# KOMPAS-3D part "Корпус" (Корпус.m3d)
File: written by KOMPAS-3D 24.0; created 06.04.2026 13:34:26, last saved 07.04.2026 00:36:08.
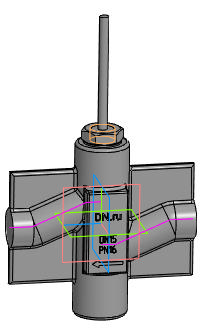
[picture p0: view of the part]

Document properties: Автор: R2D2; Полное имя файла: E:\Работа\Зайцев\Солянка\VSR1-13V-PED-F Клапан запорно-регулирующий DN.ru\DN15\DN15 Kv0.16\исходные материалы\Корпус.m3d

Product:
- Body: Труба / Нестандартная труба / L = 62.8 мм  | qty 1
    Материал: Нестандартная труба (density 7856 kg/m3)
    Масса: 1.53897
    Раздел спецификации: Детали
    Примечание: 0,24 кг
    additional columns: Pipeline; 0.025; 0; 0; 0.002; 0.06281; true; 0.04
- Body: Труба / Нестандартная труба / L = 62.8 мм  | qty 1
    Материал: Нестандартная труба (density 7856 kg/m3)
    Масса: 1.53897
    Раздел спецификации: Детали
    Форматы листов документа: БЧ
    Примечание: 0,24 кг
    additional columns: Pipeline; 0.025; 0; 0; 0.002; 0.06281; true; 0.04
- Component [standard]: Гайка М16-6H ГОСТ 5916-70  | qty 1  | Масса: 0.01768; Рассекать на разрезах: no; source file: C:\Program Files\ASCON\KOMPAS-3D v24\Libs\PolynomLib\DATA\vault\Methods\Kompas\3D\PLib_Nut_OST92_900.m3d
- Part/product: Корпус
    Масса: 1.53897

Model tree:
1. Эскиз:1
2. Труба:1  (labels: {F703FF30-5BE6-4673-A7F1-8EDA1BE1E2D1}; SHAPEOBJECT3D_ATTR_BUTT; SHAPEOBJECT3D_ATTR_VALID; SHAPEOBJECT3D_ATTR_BUTT_AREA)
     PIPE_D = 25; PIPE_R = 7
3. Труба:2  (labels: {F703FF30-5BE6-4673-A7F1-8EDA1BE1E2D1}; SHAPEOBJECT3D_ATTR_BUTT; SHAPEOBJECT3D_ATTR_VALID; SHAPEOBJECT3D_ATTR_BUTT_AREA)
     PIPE_D = 25; PIPE_R = 7
4. Эскиз:2
5. Элемент выдавливания:1
     Расстояние 1 = 55; Расстояние 2 = 60
6. Эскиз:3  (with: Ребро.Труба:2)
7. Элемент выдавливания:2
     Расстояние 1 = 6
8. Эскиз:4  (with: Грань.Элемент выдавливания:1)
9. Элемент выдавливания:3
     Расстояние 1 = 1
10. Эскиз:5  (with: Грань.Элемент выдавливания:3)
11. Элемент выдавливания:4
     Расстояние 1 = 7.5; Смещение 1 = 0.5
12. Эскиз:6
13. Элемент выдавливания:5
     Расстояние 1 = 139
14. Эскиз:7
15. Элемент выдавливания:6  (with: Грань.Элемент выдавливания:1)
     Расстояние 1 = 21.5; Смещение 1 = 4
16. Эскиз:8  (with: Грань.Элемент выдавливания:6)
17. Элемент выдавливания:7
     Расстояние 1 = 0.5
18. Скругление:3  (with: Ребро.Элемент выдавливания:2, Грань.Элемент выдавливания:2)
     Радиус = 2
19. Скругление:4  (with: Грань.Элемент выдавливания:1)
     Радиус = 2
20. Скругление:5  (with: Грань.Элемент выдавливания:6, Грань.Элемент выдавливания:3, Грань.Элемент выдавливания:1)
     Радиус = 1

Referenced files in C:\Program Files\ASCON\KOMPAS-3D v24\Libs\Pipeline\: StylesTemplate.a3d, TemplateHPH, InsulationStylesTemplate.a3d, Insulation
Referenced files in C:\Program Files\ASCON\KOMPAS-3D v24\Templates\: Констр. чертеж А3 гориз. перв. лист.cdt
Referenced files in E:\Работа\Зайцев\Солянка\VSR1-13V-PED-F Клапан запорно-регулирующий DN.ru\DN15\DN15 Kv0.16\исходные материалы\: 
Referenced files in C:\Program Files\ASCON\KOMPAS-3D v24\Libs\PolynomLib\DATA\vault\Methods\Kompas\3D\: PLib_Nut_OST92_900.m3d
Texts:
  Отводы ГОСТ 17375-2001
  Констр. чертеж А3 гориз. перв. лист.cdt
  BOSimple***PART:2c8e7818-1586-f79e-db7d-bc045ba468e4***SHORTLOC:Root±30±10±20±©{}110±10±50±80[Нет;Без покрытия;Без указания материала;-;16;2;24]
  DN15
  PN16
  bcut1
  hole1
  hcut1
  hole2
  cut1
  Труба / Нестандартная труба / L = %s мм
  Plane. Начало координат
